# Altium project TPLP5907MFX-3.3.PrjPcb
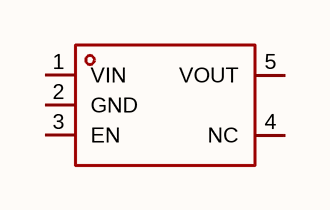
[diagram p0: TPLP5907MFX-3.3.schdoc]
1 sheet, 1 parts. Net scope: global (net labels, ports and power ports of the same name join across sheets).

## Sheet TPLP5907MFX-3.3.schdoc
size 127 x 101 mm

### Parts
U?  tplp5907mfx-3.3  [SOT-23-5_L2.9-W1.6-P0.95-LS2.8-BR]  (value not drawn)

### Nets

Not connected (* = marked no-connect by the designer): U? 1(VIN) 2(GND) 3(EN) 4(NC) 5(VOUT)

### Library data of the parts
U? = tplp5907mfx-3.3: 输出极性:正极;工作电压:5.5V;输出电压:3.3V;输出电流:300mA;电源纹波抑制比(PSRR):75dB@(1kHz);输出类型:固定;; Manufacturer: TECH PUBLIC(台舟); AddInBom: yes; ModelId: 7ba65df16e7b4570af156e925f9c37fe; ModelTransform: 114.173,114.173,0,90,0,0,0,0,0; Output Configuration: 正极; Voltage - Supply: 5.5V; Output Voltage: 3.3V; Output Current: 300mA; Voltage Dropout: 200mV@(300mA); standby current: 2uA; Noise: 51uVrms; Output Type: 固定; Number of Outputs: 1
